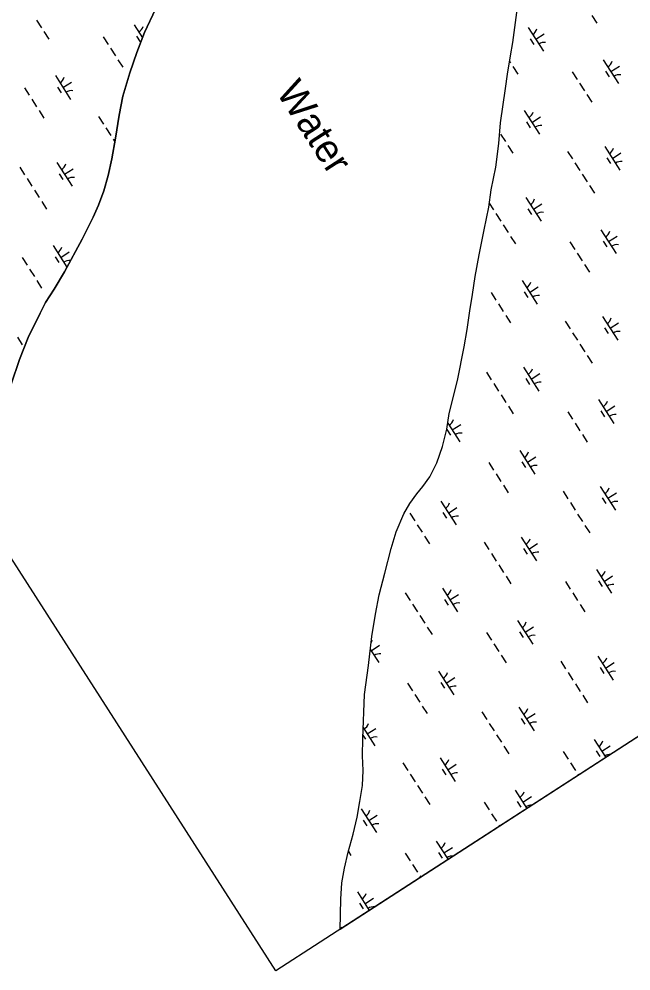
# Model space of a CAD drawing. Extents: x 3937982 to 3958556, y 219448 to 241894.
# Drawn here: x 3949325 to 3950410, y 222174 to 223860 of the extents above; entities that cross this region are included whole.
import ezdxf

# ---------------------------------------------------------------- set-up
doc = ezdxf.new("R2010")
doc.units = 0
for name, color, linetype in [('V-GRID-FRAM', 7, 'Continuous'), ('V-RIVR-IDEN', 7, 'Continuous'), ('V-TOPO-SHOR', 7, 'Continuous'), ('V-WETL-SWMP', 7, 'Continuous')]:
    doc.layers.add(name, color=color, linetype=linetype)

msp = doc.modelspace()

# ---------------------------------------------------------------- linework, layer by layer
at = {"layer": 'V-GRID-FRAM'}
msp.add_lwpolyline([(3948998.173, 239513.74), (3957109.469, 226912.286), (3949780.097, 222173.81), (3941699.799, 234772.334), (3948998.173, 239513.74)], dxfattribs=at)
at = {"layer": 'V-TOPO-SHOR'}
for points in [[(3950204.758, 223854.539), (3950210.498, 223895.131)], [(3949310.976, 223213.292), (3949325.797, 223257.316), (3949341.427, 223295.886), (3949362.751, 223339.429), (3949371.742, 223357.94), (3949387.2, 223381.949), (3949405.479, 223412.735), (3949436.858, 223470.636), (3949447.393, 223491.755), (3949456.65, 223509.228), (3949466.144, 223530.343), (3949475.094, 223555.873), (3949483.251, 223583.481), (3949489.32, 223612.894), (3949496.123, 223649.332), (3949502.644, 223690.187), (3949508.948, 223723.762), (3949521.182, 223765.171), (3949533.97, 223801.384), (3949547.54, 223836.82), (3949566.8, 223877.751)], [(3949894.159, 222247.551), (3949895.135, 222301.138), (3949897.306, 222329.748), (3949902.092, 222356.036), (3949908.684, 222384.413), (3949917.339, 222415.922), (3949924.182, 222446.12), (3949929.216, 222474.228), (3949933.99, 222502.593), (3949935.134, 222528.859), (3949933.94, 222555.11), (3949934.28, 222585.789), (3949937.463, 222663.804), (3949944.443, 222714.803), (3949950.64, 222766.574), (3949956.909, 222805.869), (3949963.206, 222839.964), (3949973.379, 222878.762), (3949984.821, 222922.507), (3949993.75, 222951.677), (3950007.083, 222983.474), (3950017.892, 223001.996), (3950030.27, 223019.228), (3950040.594, 223032.288), (3950052.972, 223049.258), (3950065.827, 223074.032), (3950075.795, 223103.208), (3950083.416, 223133.672), (3950087.673, 223161.255), (3950101.889, 223219.836), (3950114.277, 223279.445), (3950119.557, 223310.412), (3950124.302, 223343.459), (3950128.552, 223372.342), (3950133.565, 223404.088), (3950140.358, 223442.607), (3950149.2, 223486.856), (3950157.543, 223526.941), (3950162.043, 223557.647), (3950169.868, 223597.731), (3950175.34, 223639.62), (3950178.504, 223676.296), (3950187.245, 223737.443), (3950190.735, 223762.943), (3950196.269, 223794.953), (3950200.287, 223818.894), (3950204.758, 223854.539)]]:
    msp.add_lwpolyline(points, dxfattribs=at)
at = {"layer": 'V-WETL-SWMP'}
for p, q in [((3950204.758, 223854.539), (3950210.499, 223895.13)), ((3949566.799, 223877.752), (3949547.541, 223836.821)), ((3950340.267, 223866.394), (3950348.926, 223852.94)), ((3949356.285, 223858.463), (3949364.945, 223845.009)), ((3949529.299, 223850.121), (3949543.93, 223827.391)), ((3950200.287, 223818.895), (3950204.758, 223854.539)), ((3950227.295, 223845.501), (3950254.357, 223803.458)), ((3949369.274, 223838.283), (3949377.934, 223824.829)), ((3949474.433, 223828.724), (3949483.093, 223815.27)), ((3949533.095, 223829.969), (3949539.59, 223819.878)), ((3949547.541, 223836.821), (3949533.97, 223801.384)), ((3949542.83, 223829.099), (3949545.158, 223830.598)), ((3950240.826, 223824.48), (3950255.961, 223834.222)), ((3950196.268, 223794.953), (3950200.287, 223818.895)), ((3950231.091, 223825.349), (3950237.585, 223815.258)), ((3949487.423, 223808.543), (3949496.083, 223795.089)), ((3949533.97, 223801.384), (3949521.183, 223765.171)), ((3950190.736, 223762.942), (3950196.268, 223794.953)), ((3949500.413, 223788.363), (3949509.073, 223774.909)), ((3950194.61, 223785.358), (3950196.069, 223783.091)), ((3950360.424, 223788.203), (3950387.486, 223746.159)), ((3949521.183, 223765.171), (3949508.947, 223723.762)), ((3950187.246, 223737.443), (3950190.736, 223762.942)), ((3950200.399, 223776.364), (3950209.059, 223762.91)), ((3950305.558, 223766.806), (3950314.218, 223753.352)), ((3950364.22, 223768.05), (3950370.715, 223757.96)), ((3950373.955, 223767.181), (3950389.09, 223776.923)), ((3949389.432, 223760.092), (3949416.494, 223718.048)), ((3949402.963, 223739.07), (3949418.098, 223748.812)), ((3950318.548, 223746.625), (3950327.208, 223733.171)), ((3949334.566, 223738.695), (3949343.226, 223725.241)), ((3949393.228, 223739.939), (3949399.723, 223729.849)), ((3950178.505, 223676.296), (3950187.246, 223737.443)), ((3949347.556, 223718.514), (3949356.216, 223705.06)), ((3949508.947, 223723.762), (3949502.644, 223690.187)), ((3950331.538, 223726.444), (3950340.197, 223712.99)), ((3949360.546, 223698.333), (3949369.205, 223684.879)), ((3950220.557, 223698.173), (3950247.619, 223656.13)), ((3949466.133, 223687.806), (3949474.793, 223674.353)), ((3949502.644, 223690.187), (3949496.124, 223649.331)), ((3950175.341, 223639.62), (3950178.505, 223676.296)), ((3950224.353, 223678.021), (3950230.847, 223667.93)), ((3950234.088, 223677.152), (3950249.223, 223686.894)), ((3949479.123, 223667.626), (3949487.782, 223654.172)), ((3949496.124, 223649.331), (3949489.319, 223612.894)), ((3949492.112, 223647.445), (3949494.949, 223643.039)), ((3950178.68, 223656.595), (3950187.34, 223643.141)), ((3950169.867, 223597.73), (3950175.341, 223639.62)), ((3950191.67, 223636.415), (3950200.33, 223622.961)), ((3950297.257, 223625.888), (3950305.917, 223612.434)), ((3950363.122, 223634.483), (3950390.185, 223592.44)), ((3949489.319, 223612.894), (3949483.252, 223583.48)), ((3950366.918, 223614.331), (3950373.413, 223604.24)), ((3950376.654, 223613.461), (3950391.789, 223623.204)), ((3949326.265, 223597.777), (3949334.925, 223584.323)), ((3949392.13, 223606.372), (3949419.193, 223564.329)), ((3949405.662, 223585.35), (3949420.797, 223595.093)), ((3950162.043, 223557.647), (3950169.867, 223597.73)), ((3950310.247, 223605.707), (3950318.907, 223592.253)), ((3949339.255, 223577.596), (3949347.915, 223564.142)), ((3949395.926, 223586.22), (3949402.421, 223576.129)), ((3949483.252, 223583.48), (3949475.094, 223555.874)), ((3950323.237, 223585.527), (3950331.897, 223572.073)), ((3950336.227, 223565.346), (3950344.887, 223551.892)), ((3949352.245, 223557.416), (3949360.905, 223543.962)), ((3949475.094, 223555.874), (3949466.145, 223530.343)), ((3950157.543, 223526.942), (3950162.043, 223557.647)), ((3950223.255, 223544.453), (3950250.317, 223502.41)), ((3949365.235, 223537.235), (3949373.895, 223523.781)), ((3949466.145, 223530.343), (3949456.649, 223509.228)), ((3950149.199, 223486.856), (3950157.543, 223526.942)), ((3950158.579, 223534.011), (3950166.05, 223522.405)), ((3950227.051, 223524.301), (3950233.546, 223514.211)), ((3950236.786, 223523.432), (3950251.922, 223533.174)), ((3949456.649, 223509.228), (3949447.392, 223491.755)), ((3950170.38, 223515.678), (3950179.04, 223502.224)), ((3949447.392, 223491.755), (3949436.857, 223470.635)), ((3950183.37, 223495.497), (3950192.03, 223482.043)), ((3950140.359, 223442.607), (3950149.199, 223486.856)), ((3950196.36, 223475.316), (3950205.02, 223461.862)), ((3950356.384, 223487.155), (3950383.447, 223445.112)), ((3950369.916, 223466.133), (3950385.051, 223475.876)), ((3949385.392, 223459.044), (3949409.923, 223420.934)), ((3949436.857, 223470.635), (3949405.479, 223412.734)), ((3950301.518, 223465.758), (3950310.178, 223452.304)), ((3950360.18, 223467.002), (3950366.675, 223456.912)), ((3949398.923, 223438.022), (3949414.059, 223447.765)), ((3950133.566, 223404.089), (3950140.359, 223442.607)), ((3950314.508, 223445.577), (3950323.168, 223432.123)), ((3949330.526, 223437.647), (3949339.186, 223424.193)), ((3949389.188, 223438.891), (3949395.683, 223428.801)), ((3950327.498, 223425.396), (3950336.158, 223411.942)), ((3949343.516, 223417.466), (3949352.176, 223404.012)), ((3949405.479, 223412.734), (3949387.2, 223381.949)), ((3949356.506, 223397.285), (3949365.166, 223383.831)), ((3950128.552, 223372.342), (3950133.566, 223404.089)), ((3950216.517, 223397.125), (3950243.579, 223355.082)), ((3949387.2, 223381.949), (3949371.742, 223357.94)), ((3950124.302, 223343.459), (3950128.552, 223372.342)), ((3950161.651, 223375.728), (3950170.311, 223362.274)), ((3950220.313, 223376.973), (3950226.808, 223366.883)), ((3950230.048, 223376.104), (3950245.184, 223385.846)), ((3949371.742, 223357.94), (3949362.752, 223339.428)), ((3950174.641, 223355.548), (3950183.301, 223342.094)), ((3949362.752, 223339.428), (3949341.428, 223295.886)), ((3950119.556, 223310.413), (3950124.302, 223343.459)), ((3950187.631, 223335.367), (3950196.291, 223321.913)), ((3950293.218, 223324.84), (3950301.878, 223311.386)), ((3950359.083, 223333.435), (3950386.145, 223291.392)), ((3950372.614, 223312.414), (3950387.75, 223322.156)), ((3950114.278, 223279.444), (3950119.556, 223310.413)), ((3950362.879, 223313.283), (3950369.374, 223303.192)), ((3949322.226, 223296.729), (3949330.886, 223283.275)), ((3949341.428, 223295.886), (3949325.796, 223257.316)), ((3950306.208, 223304.659), (3950314.868, 223291.206)), ((3950101.889, 223219.835), (3950114.278, 223279.444)), ((3950319.198, 223284.479), (3950327.858, 223271.025)), ((3949325.796, 223257.316), (3949310.975, 223213.292)), ((3950332.188, 223264.298), (3950340.848, 223250.844)), ((3950219.216, 223243.406), (3950246.278, 223201.362)), ((3950153.351, 223234.811), (3950162.011, 223221.357)), ((3950223.012, 223223.253), (3950229.507, 223213.163)), ((3950232.747, 223222.384), (3950247.882, 223232.126)), ((3950087.674, 223161.255), (3950101.889, 223219.835)), ((3950166.341, 223214.63), (3950175.001, 223201.176)), ((3951367.669, 223200.184), (3949894.159, 222247.551)), ((3950179.331, 223194.449), (3950187.99, 223180.995)), ((3950192.32, 223174.269), (3950200.98, 223160.815)), ((3950352.345, 223186.107), (3950379.407, 223144.064)), ((3950365.876, 223165.085), (3950381.012, 223174.828)), ((3950083.416, 223133.672), (3950087.674, 223161.255)), ((3950297.479, 223164.71), (3950306.139, 223151.256)), ((3950356.141, 223165.955), (3950362.636, 223155.864)), ((3950085.083, 223144.468), (3950106.411, 223111.333)), ((3950092.88, 223132.355), (3950108.015, 223142.097)), ((3950310.469, 223144.529), (3950319.129, 223131.075)), ((3950075.795, 223103.209), (3950083.416, 223133.672)), ((3950083.259, 223133.045), (3950089.639, 223123.133)), ((3950323.459, 223124.349), (3950332.119, 223110.895)), ((3950065.827, 223074.032), (3950075.795, 223103.209)), ((3950212.478, 223096.078), (3950239.54, 223054.034)), ((3950052.973, 223049.258), (3950065.827, 223074.032)), ((3950157.612, 223074.68), (3950166.272, 223061.227)), ((3950216.274, 223075.925), (3950222.769, 223065.835)), ((3950226.009, 223075.056), (3950241.144, 223084.798)), ((3950170.602, 223054.5), (3950179.261, 223041.046)), ((3950040.594, 223032.287), (3950052.973, 223049.258)), ((3950017.893, 223001.995), (3950030.271, 223019.227)), ((3950030.271, 223019.227), (3950040.594, 223032.287)), ((3950183.591, 223034.319), (3950192.251, 223020.865)), ((3950289.179, 223023.792), (3950297.838, 223010.339)), ((3950355.044, 223032.387), (3950382.106, 222990.344)), ((3950368.575, 223011.366), (3950383.71, 223021.108)), ((3950007.082, 222983.473), (3950017.893, 223001.995)), ((3950072.61, 223006.048), (3950099.673, 222964.005)), ((3950302.168, 223003.612), (3950310.828, 222990.158)), ((3950358.84, 223012.235), (3950365.334, 223002.145)), ((3950017.744, 222984.651), (3950026.404, 222971.197)), ((3950076.406, 222985.896), (3950082.901, 222975.805)), ((3950086.142, 222985.026), (3950101.277, 222994.769)), ((3949993.75, 222951.677), (3950007.082, 222983.473)), ((3950315.158, 222983.431), (3950323.818, 222969.977)), ((3949984.821, 222922.506), (3949993.75, 222951.677)), ((3950030.734, 222964.47), (3950039.394, 222951.016)), ((3950328.148, 222963.25), (3950336.808, 222949.796)), ((3950043.724, 222944.29), (3950052.384, 222930.836)), ((3950215.176, 222942.358), (3950242.239, 222900.315)), ((3949973.379, 222878.762), (3949984.821, 222922.506)), ((3950149.311, 222933.763), (3950157.971, 222920.309)), ((3950218.972, 222922.205), (3950225.467, 222912.115)), ((3950228.707, 222921.336), (3950243.843, 222931.079)), ((3950162.301, 222913.582), (3950170.961, 222900.128)), ((3950175.291, 222893.401), (3950183.951, 222879.948)), ((3950348.306, 222885.059), (3950375.368, 222843.016)), ((3949963.207, 222839.964), (3949973.379, 222878.762)), ((3950188.281, 222873.221), (3950196.941, 222859.767)), ((3950361.837, 222864.038), (3950376.972, 222873.78)), ((3950075.309, 222852.328), (3950102.371, 222810.285)), ((3950293.439, 222863.662), (3950302.099, 222850.208)), ((3950352.102, 222864.907), (3950358.596, 222854.817)), ((3949956.908, 222805.87), (3949963.207, 222839.964)), ((3950009.444, 222843.733), (3950018.104, 222830.28)), ((3950088.84, 222831.307), (3950103.976, 222841.049)), ((3950306.429, 222843.481), (3950315.089, 222830.028)), ((3950022.434, 222823.553), (3950031.094, 222810.099)), ((3950079.105, 222832.176), (3950085.6, 222822.086)), ((3950319.419, 222823.301), (3950328.079, 222809.847)), ((3949950.639, 222766.575), (3949956.908, 222805.87)), ((3950035.424, 222803.372), (3950044.084, 222789.918)), ((3950048.414, 222783.191), (3950057.074, 222769.737)), ((3950208.438, 222795.03), (3950235.501, 222752.987)), ((3950221.969, 222774.008), (3950237.105, 222783.751)), ((3949944.443, 222714.802), (3949950.639, 222766.575)), ((3950153.572, 222773.633), (3950162.232, 222760.179)), ((3950212.234, 222774.877), (3950218.729, 222764.787)), ((3949948.973, 222741.277), (3949964.108, 222751.02)), ((3950166.562, 222753.452), (3950175.222, 222739.998)), ((3949947.825, 222743.061), (3949962.504, 222720.256)), ((3950179.552, 222733.271), (3950188.212, 222719.817)), ((3949937.463, 222663.804), (3949944.443, 222714.802)), ((3950285.139, 222722.745), (3950293.799, 222709.291)), ((3950351.004, 222731.34), (3950378.066, 222689.296)), ((3950364.535, 222710.318), (3950379.671, 222720.06)), ((3950068.571, 222705), (3950095.633, 222662.957)), ((3950298.129, 222702.564), (3950306.789, 222689.11)), ((3950354.8, 222711.187), (3950361.295, 222701.097)), ((3950013.705, 222683.603), (3950022.365, 222670.149)), ((3950072.367, 222684.848), (3950078.862, 222674.758)), ((3950082.102, 222683.979), (3950097.238, 222693.721)), ((3950311.119, 222682.383), (3950319.779, 222668.929)), ((3949934.281, 222585.79), (3949937.463, 222663.804)), ((3950026.695, 222663.422), (3950035.355, 222649.969)), ((3950324.109, 222662.202), (3950332.769, 222648.749)), ((3950039.685, 222643.242), (3950048.345, 222629.788)), ((3950145.272, 222632.715), (3950153.932, 222619.261)), ((3950211.137, 222641.31), (3950238.199, 222599.267)), ((3950214.933, 222621.158), (3950221.428, 222611.067)), ((3950224.668, 222620.289), (3950239.804, 222630.031)), ((3949935.068, 222605.084), (3949955.766, 222572.928)), ((3949942.235, 222593.949), (3949957.37, 222603.692)), ((3950158.262, 222612.534), (3950166.922, 222599.081)), ((3949933.941, 222555.11), (3949934.281, 222585.79)), ((3949934.521, 222591.678), (3949938.995, 222584.728)), ((3950171.252, 222592.354), (3950179.912, 222578.9)), ((3950344.266, 222584.012), (3950364.931, 222551.908)), ((3950184.242, 222572.173), (3950192.902, 222558.719)), ((3950348.062, 222563.859), (3950354.557, 222553.769)), ((3950357.797, 222562.99), (3950372.933, 222572.732)), ((3949935.135, 222528.859), (3949933.941, 222555.11)), ((3950071.27, 222551.281), (3950098.332, 222509.237)), ((3950289.4, 222562.614), (3950298.06, 222549.161)), ((3950005.405, 222542.686), (3950014.065, 222529.232)), ((3950075.066, 222531.128), (3950081.561, 222521.038)), ((3950084.801, 222530.259), (3950099.936, 222540.001)), ((3950302.39, 222542.434), (3950311.05, 222528.98)), ((3949933.989, 222502.594), (3949935.135, 222528.859)), ((3950018.395, 222522.505), (3950027.054, 222509.051)), ((3950315.38, 222522.253), (3950316.462, 222520.572)), ((3949929.216, 222474.228), (3949933.989, 222502.594)), ((3950031.384, 222502.324), (3950040.044, 222488.87)), ((3950044.374, 222482.143), (3950053.034, 222468.69)), ((3950204.399, 222493.982), (3950225.243, 222461.599)), ((3950217.93, 222472.96), (3950233.066, 222482.703)), ((3949924.181, 222446.12), (3949929.216, 222474.228)), ((3950149.533, 222472.585), (3950158.193, 222459.131)), ((3950208.195, 222473.83), (3950214.69, 222463.739)), ((3949917.339, 222415.922), (3949924.181, 222446.12)), ((3949931.402, 222461.251), (3949958.465, 222419.208)), ((3949944.934, 222440.23), (3949960.069, 222449.972)), ((3950162.523, 222452.404), (3950171.183, 222438.95)), ((3949935.198, 222441.099), (3949941.693, 222431.008)), ((3950175.513, 222432.223), (3950176.774, 222430.264)), ((3949908.684, 222384.413), (3949917.339, 222415.922)), ((3950064.532, 222403.953), (3950085.555, 222371.29)), ((3949902.091, 222356.036), (3949908.684, 222384.413)), ((3949908.917, 222385.262), (3949913.167, 222378.66)), ((3950009.666, 222382.555), (3950018.325, 222369.102)), ((3950068.328, 222383.8), (3950074.823, 222373.71)), ((3950078.063, 222382.931), (3950093.198, 222392.673)), ((3950022.655, 222362.375), (3950031.315, 222348.921)), ((3949897.306, 222329.749), (3949902.091, 222356.036)), ((3949895.134, 222301.138), (3949897.306, 222329.749)), ((3950035.645, 222342.194), (3950037.087, 222339.955)), ((3949924.664, 222313.923), (3949945.868, 222280.982)), ((3949894.159, 222247.551), (3949895.134, 222301.138)), ((3949928.46, 222293.771), (3949934.955, 222283.68)), ((3949938.195, 222292.901), (3949953.331, 222302.644)), ((3949895.778, 222252.164), (3949897.399, 222249.646))]:
    msp.add_line(p, q, dxfattribs=at)
for centre, start, end in [((3949528.08, 223852.454), 301.99668, 343.540338), ((3950226.075, 223847.834), 301.99668, 343.540338), ((3950255.975, 223801.382), 81.996677, 123.540335), ((3950359.205, 223790.535), 301.99668, 343.540338), ((3950389.105, 223744.084), 81.996677, 123.540335), ((3949388.213, 223762.424), 301.99668, 343.540338), ((3949418.113, 223715.973), 81.996677, 123.540335), ((3950219.337, 223700.506), 301.99668, 343.540338), ((3950249.237, 223654.054), 81.996677, 123.540335), ((3950361.903, 223636.816), 301.99668, 343.540338), ((3949390.911, 223608.705), 301.99668, 343.540338), ((3950391.803, 223590.364), 81.996677, 123.540335), ((3949420.811, 223562.253), 81.996677, 123.540335), ((3950222.036, 223546.786), 301.99668, 343.540338), ((3950251.936, 223500.334), 81.996677, 123.540335), ((3950355.165, 223489.488), 301.99668, 343.540338), ((3950385.065, 223443.036), 81.996677, 123.540335), ((3949384.173, 223461.377), 301.99668, 343.540338), ((3949414.073, 223414.925), 83.231633, 123.540335), ((3950215.298, 223399.458), 301.99668, 343.540338), ((3950245.198, 223353.006), 81.996677, 123.540335), ((3950357.864, 223335.768), 301.99668, 343.540338), ((3950387.764, 223289.316), 81.996677, 123.540335), ((3950217.996, 223245.738), 301.99668, 343.540338), ((3950247.896, 223199.287), 81.996677, 123.540335), ((3950351.126, 223188.44), 301.99668, 343.540338), ((3950381.026, 223141.988), 81.996677, 123.540335), ((3950078.129, 223155.709), 301.99668, 343.540338), ((3950108.029, 223109.257), 81.996677, 123.540335), ((3950211.258, 223098.41), 301.99668, 343.540338), ((3950241.158, 223051.959), 81.996677, 123.540335), ((3950353.824, 223034.72), 301.99668, 343.540338), ((3950071.391, 223008.381), 301.99668, 343.540338), ((3950383.724, 222988.268), 81.996677, 123.540335), ((3950101.291, 222961.929), 81.996677, 123.540335), ((3950213.957, 222944.691), 301.99668, 343.540338), ((3950243.857, 222898.239), 81.996677, 123.540335), ((3950347.086, 222887.392), 301.99668, 343.540338), ((3950074.09, 222854.661), 301.99668, 343.540338), ((3950376.986, 222840.94), 81.996677, 123.540335), ((3950103.99, 222808.209), 81.996677, 123.540335), ((3950207.219, 222797.363), 301.99668, 343.540338), ((3950237.119, 222750.911), 81.996677, 123.540335), ((3949934.223, 222764.632), 328.93438, 343.540338), ((3949964.123, 222718.18), 81.996677, 123.540335), ((3950349.785, 222733.672), 301.99668, 343.540338), ((3950067.352, 222707.333), 301.99668, 343.540338), ((3950379.685, 222687.221), 81.996677, 123.540335), ((3950097.252, 222660.881), 81.996677, 123.540335), ((3950209.918, 222643.643), 301.99668, 343.540338), ((3950239.818, 222597.191), 81.996677, 123.540335), ((3949927.485, 222617.304), 301.99668, 343.540338), ((3949957.385, 222570.852), 81.996677, 123.540335), ((3950343.047, 222586.344), 301.99668, 343.540338), ((3950070.05, 222553.613), 301.99668, 343.540338), ((3950372.947, 222539.893), 87.919602, 123.540335), ((3950099.95, 222507.162), 81.996677, 123.540335), ((3950203.18, 222496.315), 301.99668, 343.540338), ((3950233.08, 222449.863), 86.077818, 123.540335), ((3949930.183, 222463.584), 301.99668, 343.540338), ((3949960.083, 222417.132), 81.996677, 123.540335), ((3950063.312, 222406.285), 301.99668, 343.540338), ((3950093.212, 222359.834), 84.311996, 123.540335), ((3949923.445, 222316.256), 301.99668, 343.540338), ((3949953.345, 222269.804), 82.611948, 123.540335)]:
    msp.add_arc(centre, 17.623, start, end, dxfattribs=at)

# ---------------------------------------------------------------- texts
at = {"layer": 'V-RIVR-IDEN'}
msp.add_text('Water', height=49.9999, rotation=302.768556, dxfattribs=at).set_placement((3949779.705, 223731.071))

doc.saveas('drawing.dxf')
